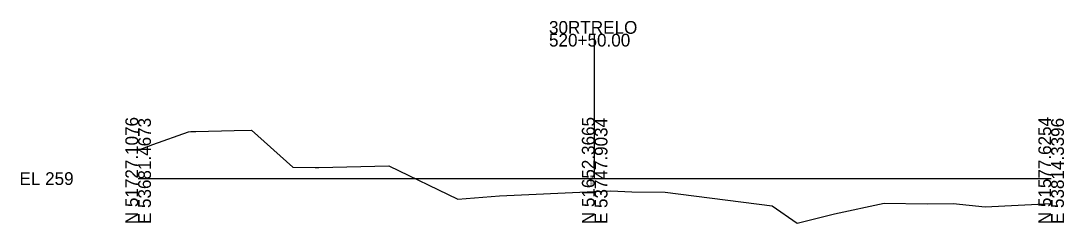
# Model space of a CAD drawing. Extents: x 12366 to 12594, y 96215 to 100251.
# Drawn here: x 12365.6 to 12594.1, y 98714.8 to 98759.3 of the extents above; entities that cross this region are included whole.
import ezdxf

# ---------------------------------------------------------------- set-up
doc = ezdxf.new("R2010")
doc.units = 0
for name, color, linetype in [('Level 10', 7, 'Continuous'), ('Level 60', 7, 'Continuous'), ('Level 63', 7, 'Continuous')]:
    doc.layers.add(name, color=color, linetype=linetype)

msp = doc.modelspace()

# ---------------------------------------------------------------- linework, layer by layer
at = {"layer": 'Level 60'}
for p, q in [((12394.52, 98732.16), (12402.34, 98734.94)), ((12402.34, 98734.94), (12402.82, 98734.98)), ((12402.82, 98734.98), (12403.96, 98734.98)), ((12403.96, 98734.98), (12412.35, 98735.17)), ((12412.35, 98735.17), (12416.14, 98735.24)), ((12416.14, 98735.24), (12425.22, 98727.18)), ((12391.3, 98730.85), (12394.52, 98732.16)), ((12425.22, 98727.18), (12430.05, 98727.06)), ((12430.05, 98727.06), (12430.86, 98727.08)), ((12430.86, 98727.08), (12446.23, 98727.45)), ((12446.23, 98727.45), (12461.3, 98720.14)), ((12461.3, 98720.14), (12470.43, 98720.83)), ((12470.43, 98720.83), (12491.3, 98721.82)), ((12491.3, 98721.82), (12494.84, 98721.98)), ((12494.84, 98721.98), (12499.46, 98721.75)), ((12499.46, 98721.75), (12506.72, 98721.65)), ((12506.72, 98721.65), (12530.18, 98718.68)), ((12530.18, 98718.68), (12535.68, 98714.85)), ((12543.81, 98716.91), (12554.7, 98719.21)), ((12554.7, 98719.21), (12564.16, 98719.12)), ((12564.16, 98719.12), (12569.87, 98719.18)), ((12569.87, 98719.18), (12576.88, 98718.45)), ((12576.88, 98718.45), (12591.3, 98719.19)), ((12535.68, 98714.85), (12543.81, 98716.91))]:
    msp.add_line(p, q, dxfattribs=at)
at = {"layer": 'Level 63'}
for p, q in [((12491.3, 98724.64), (12491.3, 98756.44)), ((12391.3, 98724.64), (12491.3, 98724.64)), ((12491.3, 98724.64), (12591.3, 98724.64))]:
    msp.add_line(p, q, dxfattribs=at)

# ---------------------------------------------------------------- texts
at = {"layer": 'Level 10'}
msp.add_text('256.18', height=0.6, rotation=90, dxfattribs=at).set_placement((12490.9, 98722.82))
at = {"layer": 'Level 63'}
for s, p in [('30RTRELO', (12481.3, 98756.44)), ('520+50.00', (12481.3, 98753.64)), ('EL 259', (12365.3, 98723.24))]:
    msp.add_text(s, height=2.8, dxfattribs=at).set_placement(p)
for s, p in [('N 51727.1076', (12391.3, 98714.64)), ('E 53681.4673', (12394.1, 98714.64)), ('N 51652.3665', (12491.3, 98714.64)), ('E 53747.9034', (12494.1, 98714.64)), ('N 51577.6254', (12591.3, 98714.64)), ('E 53814.3396', (12594.1, 98714.64))]:
    msp.add_text(s, height=2.8, rotation=90, dxfattribs=at).set_placement(p)

doc.saveas('drawing.dxf')
